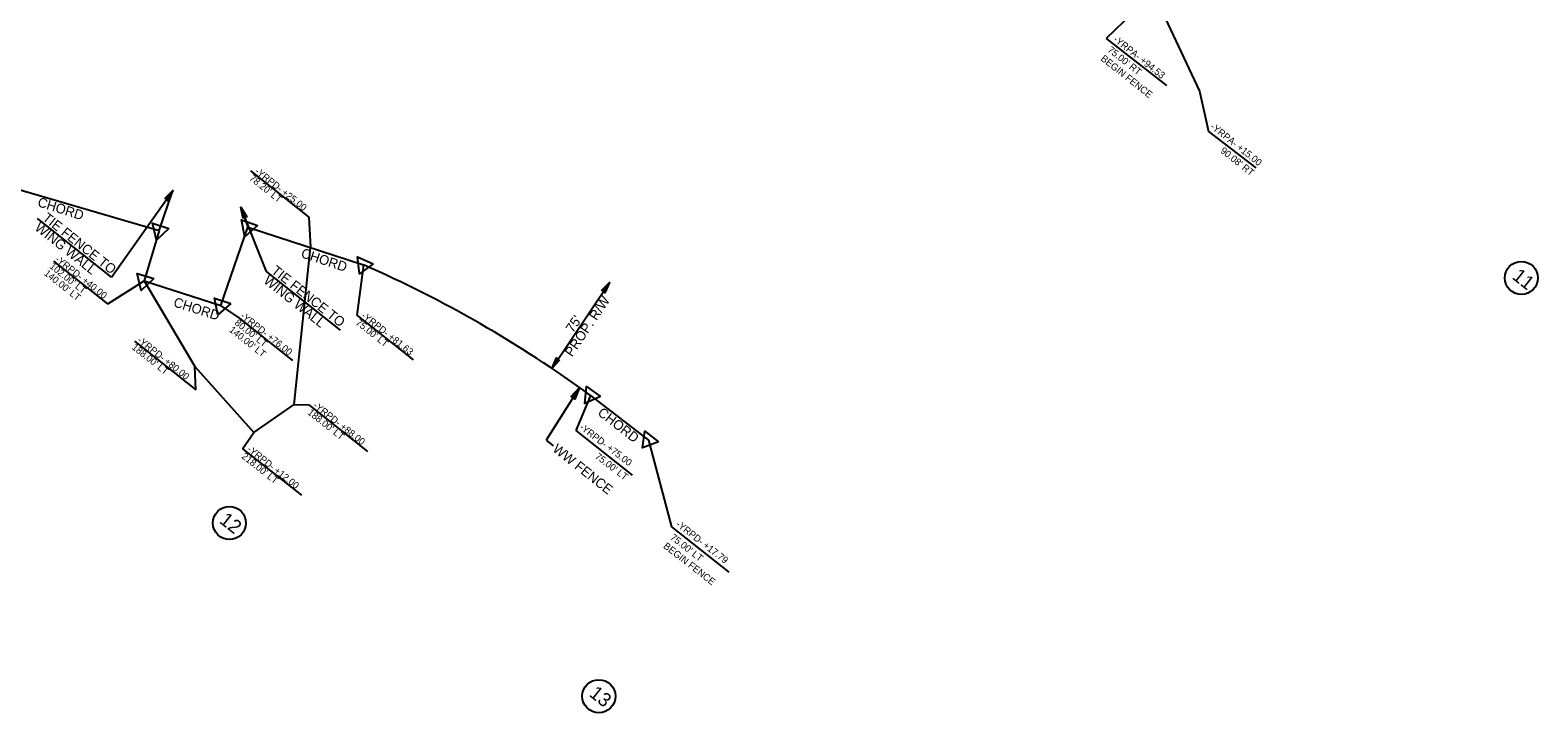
# Model space of a CAD drawing. Extents: x 1779796 to 1783527, y 810952 to 815815.
# Drawn here: x 1781820 to 1782914, y 812255 to 812750 of the extents above; entities that cross this region are included whole.
import ezdxf

# ---------------------------------------------------------------- set-up
doc = ezdxf.new("R2010")
doc.units = 0
for name, color, linetype in [('Prop Dimension', 7, 'Continuous'), ('Prop Dimension Text', 7, 'Continuous'), ('Prop Easement Construction', 7, 'Continuous'), ('Prop Easement Construction Station Offsets', 7, 'Continuous'), ('Prop Easement Temporary Drainage', 7, 'Continuous'), ('Prop Easement Temporary Drainage Station Offsets', 7, 'Continuous'), ('Prop Fence Woven Wire', 7, 'Continuous'), ('Prop Parcel Number CELL', 7, 'Continuous'), ('Prop Parcel Number Text', 7, 'Continuous'), ('Prop ROW Marker CELL', 7, 'Continuous'), ('Prop ROW RW CA Lines', 7, 'Continuous'), ('Prop ROW Station Offsets', 7, 'Continuous'), ('Prop Terminator CELL', 7, 'Continuous')]:
    doc.layers.add(name, color=color, linetype=linetype)

msp = doc.modelspace()

# ---------------------------------------------------------------- linework, layer by layer
at = {"layer": 'Prop Dimension'}
for p, q in [((1781879.1, 812571.4), (1781923.5, 812634.1)), ((1781991.5, 812575.4), (1781972.9, 812622)), ((1781879.1, 812571.4), (1781825.5, 812613.8)), ((1782045.1, 812533), (1781991.5, 812575.4)), ((1782198.5, 812505.2), (1782240.3, 812567.5)), ((1782218.6, 812491.4), (1782194.3, 812453.1)), ((1782194.3, 812453.1), (1782199.4, 812449.1))]:
    msp.add_line(p, q, dxfattribs=at)
at = {"layer": 'Prop Easement Construction'}
msp.add_line((1782635.5, 812776.1), (1782668.3, 812706.1), dxfattribs=at)
at = {"layer": 'Prop Easement Construction Station Offsets'}
for p, q in [((1782668.3, 812706.1), (1782674.9, 812677)), ((1782674.9, 812677), (1782709.2, 812650.7))]:
    msp.add_line(p, q, dxfattribs=at)
at = {"layer": 'Prop Easement Temporary Drainage'}
for p, q in [((1782011.6, 812479), (1782023.5, 812592.8)), ((1781902.7, 812568.7), (1781939.6, 812506.5)), ((1781939.6, 812506.5), (1781982.3, 812458.7)), ((1781982.3, 812458.7), (1782011.6, 812479))]:
    msp.add_line(p, q, dxfattribs=at)
at = {"layer": 'Prop Easement Temporary Drainage Station Offsets'}
for p, q in [((1781979.8, 812648.5), (1782022.3, 812614.8)), ((1782022.3, 812614.8), (1782023.5, 812592.8)), ((1781895.8, 812525), (1781940.3, 812489.7)), ((1781940.3, 812489.7), (1781939.6, 812506.5)), ((1782011.6, 812479), (1782022.2, 812478.7)), ((1782022.2, 812478.7), (1782064.7, 812445)), ((1781974.2, 812446.9), (1781982.3, 812458.7)), ((1781974.2, 812446.9), (1782016.8, 812413.2))]:
    msp.add_line(p, q, dxfattribs=at)
at = {"layer": 'Prop Fence Woven Wire'}
for p, q in [((1781781.1, 812643.8), (1781913.7, 812605.1)), ((1781913.7, 812605.1), (1781923.5, 812634.1)), ((1781972.9, 812622), (1781978, 812607.5)), ((1781978, 812607.5), (1782061.8, 812580.4)), ((1782226.6, 812485.6), (1782268.7, 812453.1))]:
    msp.add_line(p, q, dxfattribs=at)
msp.add_arc((1781705.5, 811770.3), 885, 53.9225, 66.2551, dxfattribs=at)
at = {"layer": 'Prop Parcel Number CELL'}
for p, q in [((1782901.9, 812570.8), (1782901.9, 812570.8)), ((1781964.6, 812393.1), (1781964.6, 812393.1)), ((1782232.6, 812267.5), (1782232.6, 812267.5))]:
    msp.add_line(p, q, dxfattribs=at)
for centre in [(1782901.9, 812570.8), (1781964.6, 812393.1), (1782232.6, 812267.5)]:
    msp.add_circle(centre, 12, dxfattribs=at)
at = {"layer": 'Prop ROW Marker CELL'}
for p, q in [((1781978, 812607.5), (1781978, 812607.5)), ((1781913.7, 812605.1), (1781913.7, 812605.1)), ((1782061.8, 812580.4), (1782061.8, 812580.4)), ((1781902.7, 812568.7), (1781902.7, 812568.7)), ((1781958.5, 812550.8), (1781958.5, 812550.8)), ((1782226.6, 812485.6), (1782226.6, 812485.6)), ((1782268.7, 812453.1), (1782268.7, 812453.1))]:
    msp.add_line(p, q, dxfattribs=at)
for points in [[(1781920.7, 812606.7), (1781911.6, 812598.2), (1781908.8, 812610.4)], [(1781985.1, 812608.9), (1781975.7, 812600.7), (1781973.3, 812613)], [(1782069, 812581.1), (1782058.9, 812573.8), (1782057.6, 812586.2)], [(1781909.8, 812570.4), (1781900.6, 812561.8), (1781897.8, 812574)], [(1781965.6, 812552.2), (1781956.2, 812544), (1781953.8, 812556.2)], [(1782233.8, 812484.8), (1782222.4, 812479.7), (1782223.7, 812492.1)], [(1782275.8, 812451.9), (1782264.2, 812447.5), (1782266.1, 812459.8)]]:
    msp.add_lwpolyline(points, close=True, dxfattribs=at)
at = {"layer": 'Prop ROW RW CA Lines'}
for p, q in [((1781781.1, 812643.8), (1781913.7, 812605.1)), ((1781958.5, 812550.8), (1781978, 812607.5)), ((1781978, 812607.5), (1782061.8, 812580.4)), ((1781913.7, 812605.1), (1781902.7, 812568.7)), ((1781902.7, 812568.7), (1781958.5, 812550.8)), ((1782226.6, 812485.6), (1782268.7, 812453.1))]:
    msp.add_line(p, q, dxfattribs=at)
msp.add_arc((1781705.5, 811770.3), 885, 53.9225, 66.2551, dxfattribs=at)
at = {"layer": 'Prop ROW Station Offsets'}
for p, q in [((1782619.9, 812762.7), (1782600.8, 812744.4)), ((1782600.8, 812744.4), (1782644.5, 812710.4)), ((1781876.3, 812552.1), (1781837.2, 812583)), ((1782061.8, 812580.4), (1782057.1, 812543.8)), ((1782010.6, 812511), (1781971.6, 812541.9)), ((1782057.1, 812543.8), (1782098, 812511.4)), ((1782226.6, 812485.6), (1782215.9, 812460.2)), ((1782215.9, 812460.2), (1782256.8, 812427.8)), ((1782268.7, 812453.1), (1782285.4, 812390.3)), ((1782285.4, 812390.3), (1782326.9, 812357.4))]:
    msp.add_line(p, q, dxfattribs=at)
for points in [[(1781876.3, 812552.1), (1781902.7, 812568.7)], [(1781971.6, 812541.9), (1781958.5, 812550.8)]]:
    msp.add_lwpolyline(points, dxfattribs=at)
at = {"layer": 'Prop Terminator CELL'}
for points in [[(1781917.7, 812628.3), (1781923.5, 812634.1), (1781920, 812626.6), (1781919.4, 812628.3)], [(1781974.6, 812614), (1781972.9, 812622), (1781977.2, 812615), (1781975.5, 812615.4)], [(1782234.6, 812561.6), (1782240.3, 812567.5), (1782236.9, 812560), (1782236.3, 812561.6)], [(1782204.2, 812511.2), (1782198.5, 812505.2), (1782201.8, 812512.8), (1782202.5, 812511.1)], [(1782212.4, 812484.6), (1782218.6, 812491.4), (1782215.1, 812482.9), (1782214.3, 812484.7)]]:
    msp.add_lwpolyline(points, close=True, dxfattribs=at)

# ---------------------------------------------------------------- texts
at = {"layer": 'Prop Dimension Text'}
for s, rotation, p in [('CHORD', 342.367, (1781824.9, 812622.9)), ('TIE FENCE TO', 321.5251, (1781828.5, 812613.2)), ('WING WALL', 321.5251, (1781822.8, 812606.1)), ('CHORD', 341.6637, (1782016, 812585.9)), ('TIE FENCE TO', 321.5251, (1781994.5, 812574.9)), ('WING WALL', 321.5251, (1781988.8, 812567.7)), ('CHORD', 342.367, (1781923.5, 812550.3)), ('PROP. R/W', 56.1456, (1782213.2, 812513.1)), ("75'", 56.1456, (1782213.9, 812530.5)), ('CHORD', 322.2024, (1782231.2, 812471.9)), ('WW FENCE', 321.6309, (1782198.5, 812445.6))]:
    msp.add_text(s, height=7, rotation=rotation, dxfattribs=at).set_placement(p)
at = {"layer": 'Prop Easement Construction Station Offsets'}
for s, p in [('-YRPA- +15.00', (1782675.8, 812679.7)), ("90.08' RT", (1782683.1, 812662.2))]:
    msp.add_text(s, height=5, rotation=321.6167, dxfattribs=at).set_placement(p)
at = {"layer": 'Prop Easement Temporary Drainage Station Offsets'}
for s, p in [("78.20' LT", (1781978.6, 812642.2)), ('-YRPD- +25.00', (1781982.6, 812647.3)), ("188.00' LT", (1781893.4, 812519.7)), ('-YRPD- +80.00', (1781897.4, 812524.8)), ("188.00' LT", (1782020.9, 812472.4)), ('-YRPD- +88.00', (1782024.9, 812477.5)), ("218.00' LT", (1781973, 812440.6)), ('-YRPD- +12.00', (1781977, 812445.7))]:
    msp.add_text(s, height=5, rotation=321.6309, dxfattribs=at).set_placement(p)
at = {"layer": 'Prop Parcel Number Text'}
for s, p in [('11', (1782894.6, 812570.7)), ('12', (1781956.7, 812393.8)), ('13', (1782225, 812268.1))]:
    msp.add_text(s, height=10, rotation=321.6309, dxfattribs=at).set_placement(p)
at = {"layer": 'Prop ROW Station Offsets'}
for s, rotation, p in [("75.00' RT", 321.6167, (1782601.3, 812735.3)), ('-YRPA- +94.53', 321.6167, (1782605.5, 812742.9)), ('BEGIN FENCE', 321.6167, (1782596.3, 812729)), ('-YRPD- +40.00', 321.6309, (1781837.7, 812583.5)), ("140.00' LT", 321.6309, (1781829.7, 812573.3)), ("102.00' LT", 321.6309, (1781833.7, 812578.4)), ("80.00' LT", 321.6309, (1781968, 812537.4)), ('-YRPD- +76.00', 321.6309, (1781972.1, 812542.5)), ("75.00' LT", 321.6309, (1782055.8, 812537.5)), ('-YRPD- +81.63', 321.6309, (1782059.9, 812542.6)), ("140.00' LT", 321.6309, (1781964, 812532.3)), ('-YRPD- +75.00', 322.6223, (1782218.1, 812461.7)), ("75.00' LT", 322.6223, (1782229.4, 812440.5)), ('-YRPD- +17.79', 322.0546, (1782288.1, 812391.3)), ('BEGIN FENCE', 322.0546, (1782279, 812375.5)), ("75.00' LT", 322.0546, (1782284, 812381.8))]:
    msp.add_text(s, height=5, rotation=rotation, dxfattribs=at).set_placement(p)

doc.saveas('drawing.dxf')
